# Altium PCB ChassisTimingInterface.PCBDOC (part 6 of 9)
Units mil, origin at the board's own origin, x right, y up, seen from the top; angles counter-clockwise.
Board outline 7007.87 x 4368.85 mil, 10 copper layers (Top Layer, Int1 (GND), Int2 (Sign), Int3 (Sign), Int4 (PWR), Int5 (GND), Int6 (Sign), Int7 (Sign), Int8 (GND), Bottom Layer), stack 54.89 mil thick; 537 components, 525 nets, 2288 pads, 1306 vias.
Unrouted connection lines stored in the file: 373.
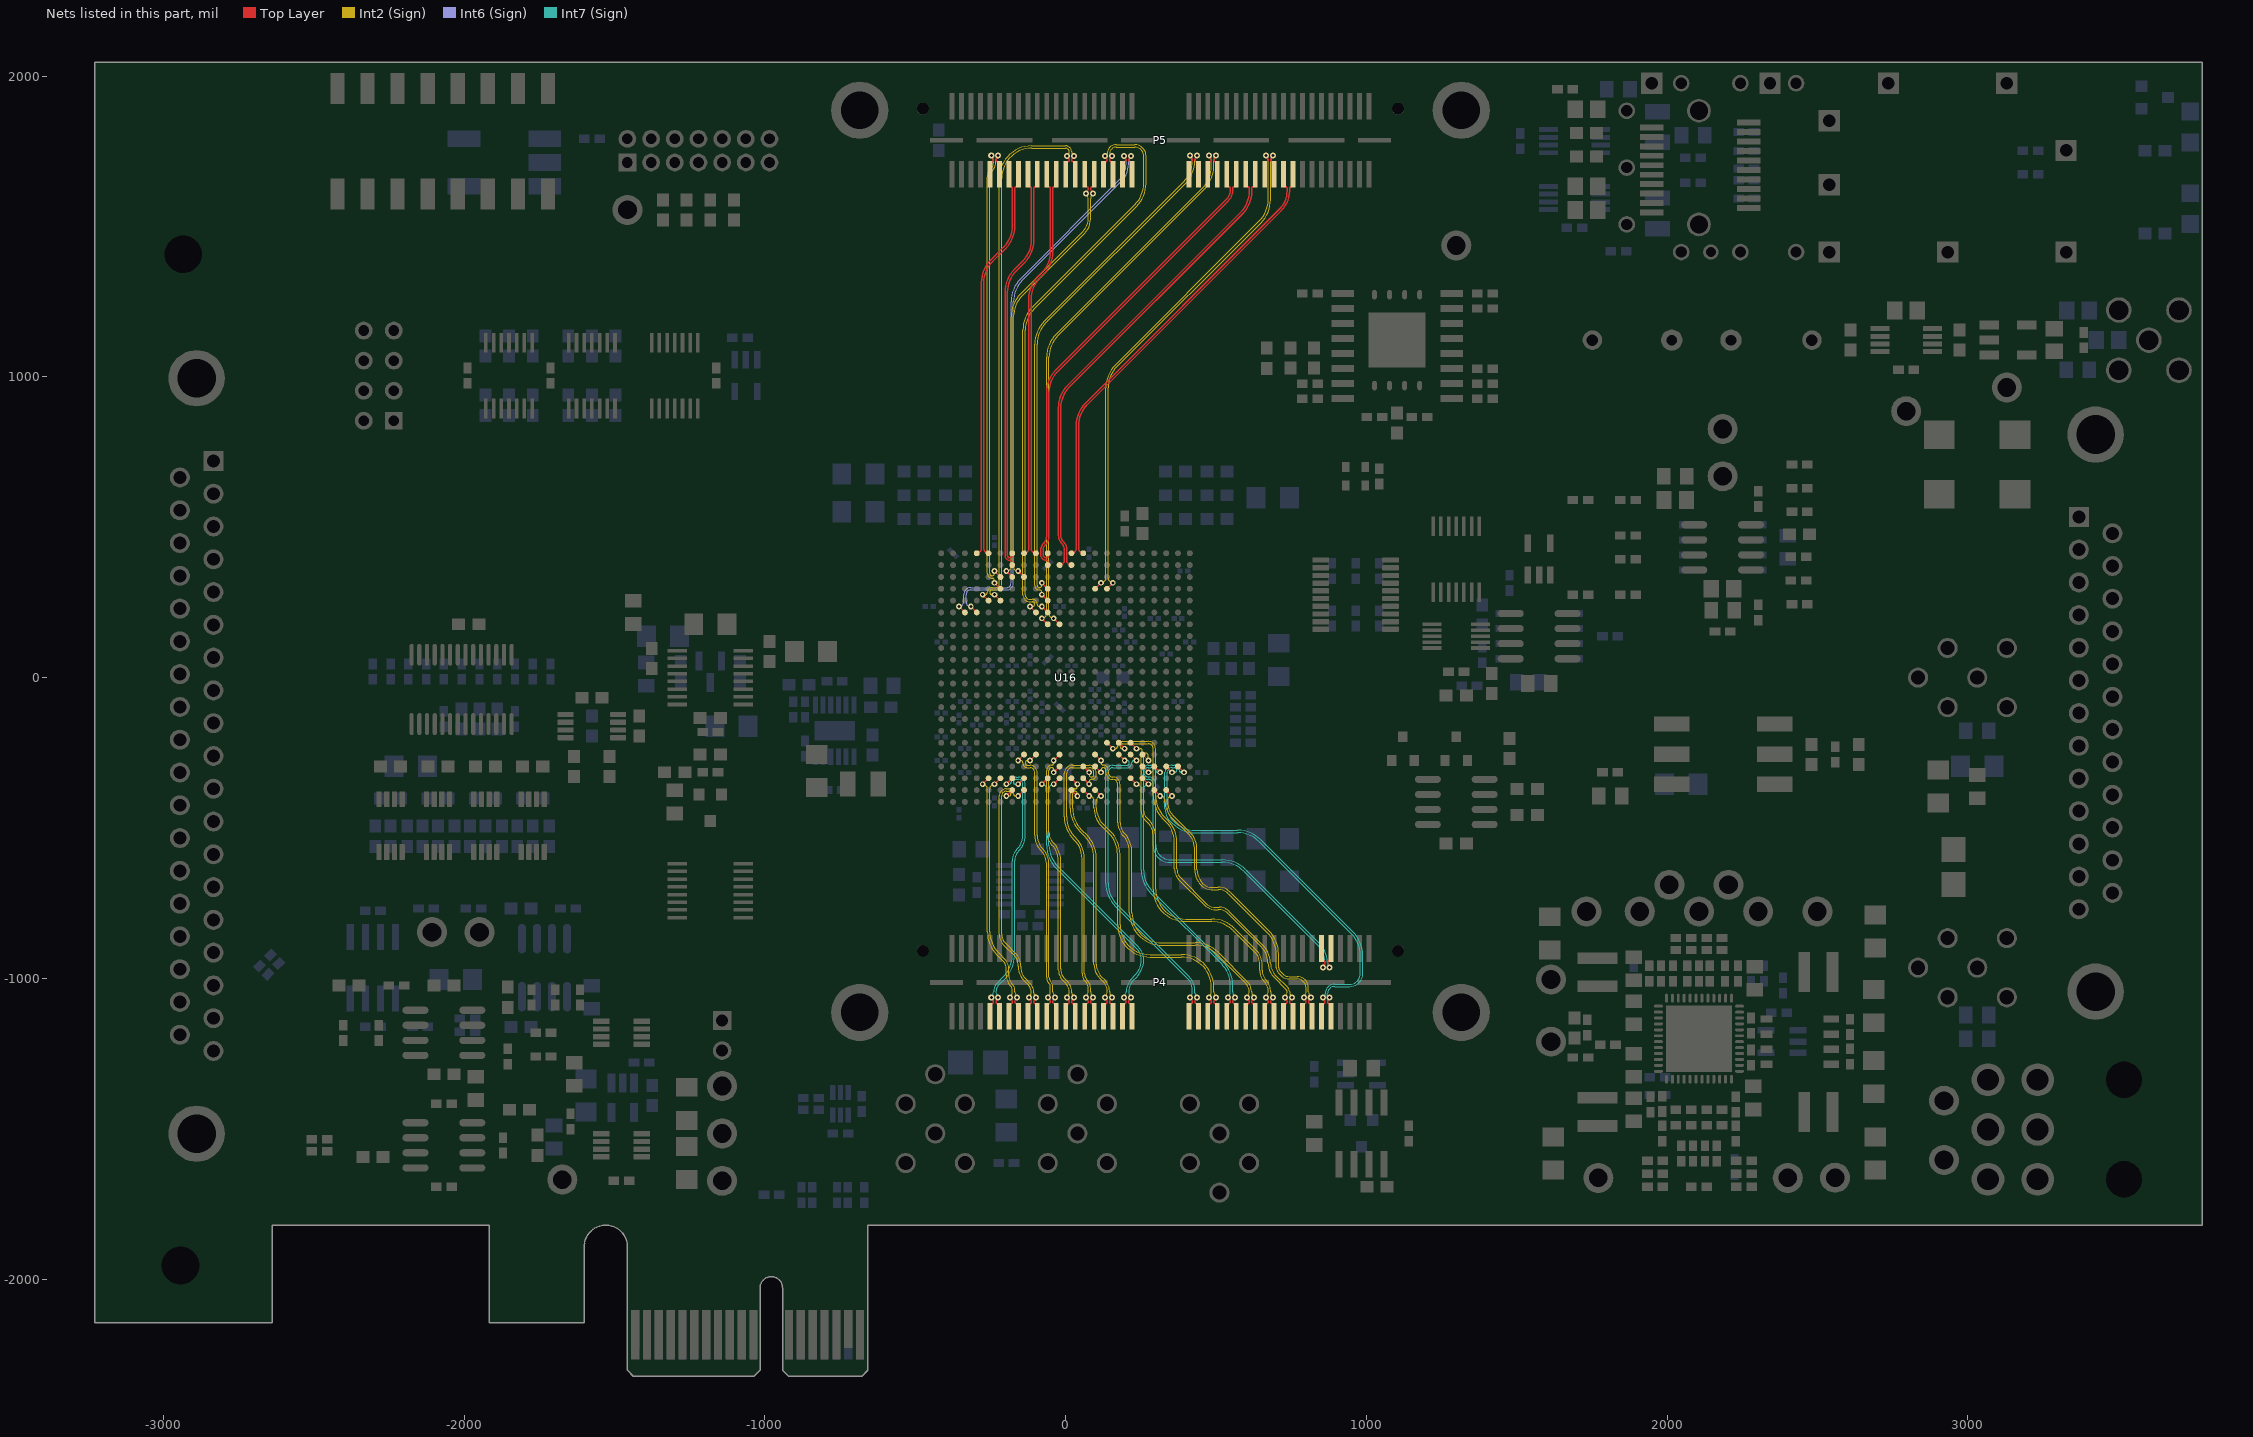
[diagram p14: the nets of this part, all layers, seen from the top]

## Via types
v1: diameter 19, hole 10, Top Layer to Bottom Layer, tented both sides, 667 vias
v2: diameter 20, hole 10, Top Layer to Bottom Layer, tented both sides, 248 vias
v3: diameter 16, hole 10, Top Layer to Bottom Layer, tented both sides, 191 vias
v4: diameter 12, hole 6, Top Layer to Bottom Layer, tented both sides, 85 vias
v5: diameter 19.68, hole 10, Top Layer to Bottom Layer, tented both sides, 50 vias
v6: diameter 17.72, hole 10, Top Layer to Bottom Layer, tented both sides, 19 vias
v7: diameter 19, hole 10, Top Layer to Bottom Layer, 15 vias
v8: diameter 23.62, hole 10, Top Layer to Bottom Layer, tented both sides, 14 vias
v9: diameter 20, hole 10, Top Layer to Bottom Layer, 11 vias
v10: diameter 16, hole 10, Top Layer to Bottom Layer, 3 vias
v11: diameter 22, hole 12, Top Layer to Bottom Layer, tented both sides, 2 vias
v12: diameter 19.02, hole 10, Top Layer to Bottom Layer, tented both sides, 1 vias

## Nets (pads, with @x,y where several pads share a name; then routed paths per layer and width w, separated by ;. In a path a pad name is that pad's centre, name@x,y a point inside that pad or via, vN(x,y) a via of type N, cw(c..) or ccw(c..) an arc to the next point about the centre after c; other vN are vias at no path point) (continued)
S1_16.S16_N: P4.70 U16.W4 | length 1228.2
  Top Layer w5: U16.W4@295.28,-295.28 v1(314.96,-314.96) ; P4.70@851.16,-900.6 851.16,-933.39 ccw(c860.13,-933.39) 853.78,-939.72 855.36,-941.3 ccw(c857.9,-938.76) 857.9,-942.35 cw(c857.9,-945.95) 860.45,-943.41 cw(c855.21,-948.64) 862.61,-948.64 862.61,-949 cw(c850.32,-949) 859.01,-957.69 857.73,-958.98 ccw(c863.31,-964.57) v2(855.41,-964.57)
  Int7 (Sign) w3: v1(314.96,-314.96) 307.15,-314.96 cw(c307.15,-307.09) 299.28,-307.09 ccw(c283.4,-307.09) 283.4,-291.21 275.59,-291.21 ccw(c275.59,-314.96) 251.84,-314.96 ccw(c275.46,-314.96) 275.46,-338.58 275.59,-338.58 cw(c275.59,-354.33) 291.34,-354.33 291.34,-558.43 ccw(c347.21,-558.43) 347.21,-614.3 521.7,-614.3 cw(c521.7,-714.3) 592.41,-643.59 840.03,-891.21 cw(c784.78,-946.46) 862.91,-946.46 cw(c843.97,-946.46) 857.36,-959.86 ccw(c862.07,-964.57) v2(855.41,-964.57)
S1_16.S16_P: P4.72 U16.V4 | length 1201.6
  Top Layer w5: U16.V4@255.91,-295.28 v1(275.59,-314.96) ; v2(878.41,-964.57) ccw(c870.52,-964.57) 876.11,-958.99 874.81,-957.69 cw(c883.51,-949) 871.21,-949 871.21,-948.64 cw(c878.62,-948.64) 873.38,-943.41 cw(c875.93,-945.95) 875.93,-942.35 ccw(c875.93,-938.76) 878.46,-941.31 880.04,-939.73 ccw(c873.7,-933.39) 882.66,-933.39 P4.72@882.66,-900.6
  Int7 (Sign) w3: v1(275.59,-314.96) 283.4,-314.96 ccw(c283.4,-307.09) 291.28,-307.09 ccw(c283.4,-307.09) 283.4,-299.21 275.59,-299.21 ccw(c275.59,-314.96) 259.84,-314.96 ccw(c275.46,-314.96) 275.46,-330.58 275.59,-330.58 cw(c275.59,-354.33) 299.34,-354.33 299.34,-555.12 ccw(c350.52,-555.12) 350.52,-606.3 521.73,-606.3 cw(c521.73,-714.21) 598.04,-637.91 845.7,-885.57 cw(c784.84,-946.44) 870.91,-946.44 ccw(c889.86,-946.46) 876.47,-959.86 cw(c871.76,-964.57) v2(878.41,-964.57)
S17_32.S17_N: P4.11 U16.G3 | length 928.7
  Top Layer w5: v2(-223.92,-1062.99) cw(c-231.82,-1062.99) -226.23,-1068.58 -227.82,-1070.16 ccw(c-219.85,-1078.13) -231.12,-1078.13 ccw(c-223.71,-1078.13) -228.95,-1083.37 ccw(c-226.41,-1080.82) -226.41,-1084.42 cw(c-226.41,-1088.01) -223.87,-1085.47 -222.29,-1087.05 cw(c-228.63,-1093.38) -219.67,-1093.38 P4.11@-219.67,-1126.17 ; v1(-196.85,-354.33) U16.G3@-177.17,-334.65
  Int7 (Sign) w3: v2(-223.92,-1062.99) ccw(c-230.58,-1062.99) -225.87,-1058.28 cw(c-212.47,-1044.89) -231.42,-1044.89 cw(c-198.2,-1044.89) -221.69,-1021.4 -200.89,-1000.6 ccw(c-277.19,-924.31) -169.29,-924.31 -169.29,-609.19 cw(c-123.09,-609.19) -155.76,-576.52 -155.67,-576.44 ccw(c-208.49,-523.62) -133.8,-523.62 -133.8,-354.27 ccw(c-157.48,-354.27) -157.48,-330.58 -163.44,-330.58 ccw(c-163.44,-348.31) -181.17,-348.31 cw(c-187.19,-348.31) -187.19,-354.33 v1(-196.85,-354.33)
S17_32.S17_P: P4.9 U16.H3 | length 903.6
  Top Layer w5: P4.9@-251.17,-1126.17 -251.17,-1093.38 cw(c-242.21,-1093.38) -248.54,-1087.04 -246.97,-1085.47 cw(c-244.43,-1088.01) -244.43,-1084.42 ccw(c-244.43,-1080.82) -241.89,-1083.37 ccw(c-247.12,-1078.13) -239.72,-1078.13 ccw(c-250.98,-1078.13) -243.02,-1070.16 -244.61,-1068.57 cw(c-239.02,-1062.99) v2(-246.92,-1062.99) ; v1(-157.48,-354.33) U16.H3@-137.8,-334.65
  Int7 (Sign) w3: v2(-246.92,-1062.99) cw(c-240.26,-1062.99) -244.97,-1058.28 ccw(c-258.37,-1044.89) -239.42,-1044.89 -239.42,-1044.76 cw(c-198.5,-1044.76) -227.43,-1015.83 -206.58,-994.97 ccw(c-277.29,-924.26) -177.29,-924.26 -177.29,-609.08 cw(c-123.36,-609.08) -161.49,-570.94 -161.42,-570.87 ccw(c-208.79,-523.5) -141.8,-523.5 -141.8,-354.27 ccw(c-157.48,-354.27) -157.48,-338.58 -163.44,-338.58 ccw(c-163.44,-348.31) -173.17,-348.31 ccw(c-167.15,-348.31) -167.15,-354.33 v1(-157.48,-354.33)
S17_32.S18_N: P4.13 U16.E3 | length 843.6
  Top Layer w5: v1(-275.59,-354.33) U16.E3@-255.91,-334.65 ; P4.13@-188.19,-1126.17 -188.19,-1093.38 cw(c-179.22,-1093.38) -185.56,-1087.04 -183.98,-1085.47 cw(c-181.45,-1088.01) -181.45,-1084.42 ccw(c-181.45,-1080.82) -178.9,-1083.37 ccw(c-184.14,-1078.13) -176.74,-1078.13 ccw(c-188,-1078.13) -180.03,-1070.16 -181.63,-1068.57 cw(c-176.04,-1062.99) v2(-183.94,-1062.99)
  Int2 (Sign) w3: v1(-275.59,-354.33) cw(c-275.59,-370.02) -259.91,-370.02 -259.91,-845.03 ccw(c-151.96,-845.03) -228.29,-921.36 -208.17,-941.48 cw(c-235.19,-968.5) -196.98,-968.5 -196.98,-989.31 ccw(c-142.96,-989.31) -181.16,-1027.51 -181.1,-1027.56 cw(c-192.37,-1038.83) -176.44,-1038.83 -176.44,-1044.89 cw(c-195.38,-1044.89) -181.99,-1058.28 ccw(c-177.28,-1062.99) v2(-183.94,-1062.99)
S17_32.S18_P: P4.15 U16.F3 | length 843.6
  Top Layer w5: v1(-236.22,-354.33) U16.F3@-216.54,-334.65 ; v2(-160.94,-1062.99) cw(c-168.83,-1062.99) -163.25,-1068.58 -164.84,-1070.16 ccw(c-156.87,-1078.13) -168.14,-1078.13 ccw(c-160.73,-1078.13) -165.97,-1083.37 ccw(c-163.42,-1080.82) -163.42,-1084.42 cw(c-163.42,-1088.01) -160.89,-1085.47 -159.3,-1087.05 cw(c-165.65,-1093.38) -156.69,-1093.38 P4.15@-156.69,-1126.17
  Int2 (Sign) w3: v1(-236.22,-354.33) ccw(c-236.22,-370.02) -251.91,-370.02 -251.91,-845.01 ccw(c-151.91,-845.01) -222.62,-915.72 -202.45,-935.89 cw(c-234.97,-968.42) -188.98,-968.42 -188.98,-989.24 ccw(c-142.78,-989.24) -175.45,-1021.9 ; -175.42,-1021.92 cw(c-192.29,-1038.79) -168.44,-1038.79 -168.44,-1044.89 ccw(c-149.49,-1044.89) -162.88,-1058.28 cw(c-167.59,-1062.99) v2(-160.94,-1062.99)
S17_32.S19_N: P4.19 U16.G2 | length 871.5
  Top Layer w5: v1(-196.85,-393.7) U16.G2@-177.17,-374.02 ; v2(-97.94,-1062.99) cw(c-105.83,-1062.99) -100.25,-1068.58 -101.84,-1070.16 ccw(c-93.87,-1078.13) -105.14,-1078.13 ccw(c-97.73,-1078.13) -102.97,-1083.37 ccw(c-100.42,-1080.82) -100.42,-1084.42 cw(c-100.42,-1088.01) -97.89,-1085.47 -96.3,-1087.05 cw(c-102.65,-1093.38) -93.69,-1093.38 P4.19@-93.69,-1126.17
  Int2 (Sign) w3: v1(-196.85,-393.7) -189.04,-393.7 ccw(c-189.04,-385.83) -181.17,-385.83 ccw(c-189.04,-385.83) -189.04,-377.95 -196.85,-377.95 ccw(c-196.85,-393.7) -212.6,-393.7 -212.6,-853.38 ccw(c-172.27,-853.38) -200.79,-881.89 -163.5,-919.17 cw(c-197.05,-952.72) -149.61,-952.72 -149.61,-960.05 ccw(c-89.97,-960.05) -132.14,-1002.22 -118.34,-1016.02 cw(c-149.49,-1047.17) -105.44,-1047.17 -105.44,-1047.24 ccw(c-92.18,-1047.24) -101.56,-1056.61 -99.88,-1058.29 cw(c-104.59,-1062.99) v2(-97.94,-1062.99)
S17_32.S19_P: P4.17 U16.H2 | length 896.6
  Top Layer w5: v1(-157.48,-393.7) U16.H2@-137.8,-374.02 ; P4.17@-125.19,-1126.17 -125.19,-1093.38 cw(c-116.22,-1093.38) -122.56,-1087.04 -120.98,-1085.47 cw(c-118.45,-1088.01) -118.45,-1084.42 ccw(c-118.45,-1080.82) -115.9,-1083.37 ccw(c-121.14,-1078.13) -113.74,-1078.13 ccw(c-125,-1078.13) -117.03,-1070.16 -118.63,-1068.57 cw(c-113.04,-1062.99) v2(-120.94,-1062.99)
  Int2 (Sign) w3: v1(-157.48,-393.7) -165.29,-393.7 cw(c-165.29,-385.83) -173.17,-385.83 ccw(c-189.04,-385.83) -189.04,-369.95 -196.85,-369.95 ccw(c-196.85,-393.7) -220.6,-393.7 -220.6,-853.41 ccw(c-172.35,-853.41) -206.47,-887.52 -169.18,-924.81 cw(c-197.13,-952.76) -157.61,-952.76 -157.61,-960.1 ccw(c-90.11,-960.1) -137.84,-1007.83 -124.05,-1021.62 cw(c-149.67,-1047.24) -113.44,-1047.24 cw(c-126.69,-1047.24) -117.31,-1056.61 -118.99,-1058.28 ccw(c-114.28,-1062.99) v2(-120.94,-1062.99)
S17_32.S20_N: P4.21 U16.H5 | length 940.2
  Top Layer w5: v1(-157.48,-275.59) U16.H5@-137.8,-255.91 ; P4.21@-62.2,-1126.17 -62.2,-1093.38 cw(c-53.24,-1093.38) -59.58,-1087.04 -58,-1085.47 cw(c-55.46,-1088.01) -55.46,-1084.42 ccw(c-55.46,-1080.82) -52.92,-1083.37 ccw(c-58.16,-1078.13) -50.75,-1078.13 ccw(c-62.02,-1078.13) -54.05,-1070.16 -55.65,-1068.57 cw(c-50.05,-1062.99) v2(-57.95,-1062.99)
  Int2 (Sign) w3: v1(-157.48,-275.59) -149.67,-275.59 cw(c-149.67,-283.46) -141.8,-283.46 ccw(c-125.92,-283.46) -125.92,-299.34 -117.98,-299.34 cw(c-117.98,-314.96) -102.36,-314.96 -102.36,-523.7 ccw(c-27.72,-523.7) -80.5,-576.48 -80.46,-576.52 cw(c-122.63,-618.69) -62.99,-618.69 -62.99,-996.77 ccw(c-36.19,-996.77) -55.17,-1015.7 -55.12,-1015.75 cw(c-66.38,-1027.01) -50.45,-1027.01 -50.45,-1044.89 cw(c-69.4,-1044.89) -56,-1058.28 ccw(c-51.29,-1062.99) v2(-57.95,-1062.99)
S17_32.S20_P: P4.23 U16.J5 | length 940.2
  Top Layer w5: v1(-118.11,-275.59) U16.J5@-98.43,-255.91 ; v2(-34.95,-1062.99) cw(c-42.85,-1062.99) -37.27,-1068.58 -38.85,-1070.16 ccw(c-30.89,-1078.13) -42.15,-1078.13 ccw(c-34.75,-1078.13) -39.98,-1083.37 ccw(c-37.44,-1080.82) -37.44,-1084.42 cw(c-37.44,-1088.01) -34.91,-1085.47 -33.32,-1087.05 cw(c-39.66,-1093.38) -30.7,-1093.38 P4.23@-30.7,-1126.17
  Int2 (Sign) w3: v1(-118.11,-275.59) -125.92,-275.59 ccw(c-125.92,-283.46) -133.8,-283.46 ccw(c-125.92,-283.46) -125.92,-291.34 -117.98,-291.34 cw(c-117.98,-314.96) -94.36,-314.96 -94.36,-523.65 ccw(c-27.58,-523.65) -74.8,-570.87 -74.76,-570.91 cw(c-122.5,-618.64) -54.99,-618.64 -54.99,-996.74 ccw(c-36.11,-996.74) -49.46,-1010.09 ; -49.43,-1010.12 cw(c-66.28,-1026.97) -42.45,-1026.97 -42.45,-1044.89 ccw(c-23.5,-1044.89) -36.9,-1058.28 cw(c-41.61,-1062.99) v2(-34.95,-1062.99)
S17_32.S21_N: P4.27 U16.L4 | length 910.6
  Top Layer w5: v1(-39.37,-314.96) U16.L4@-19.69,-295.28 ; v2(28.05,-1062.99) cw(c20.15,-1062.99) 25.73,-1068.58 24.15,-1070.16 ccw(c32.11,-1078.13) 20.85,-1078.13 ccw(c28.25,-1078.13) 23.02,-1083.37 ccw(c25.56,-1080.82) 25.56,-1084.42 cw(c25.56,-1088.01) 28.09,-1085.47 29.68,-1087.05 cw(c23.34,-1093.38) 32.3,-1093.38 P4.27@32.3,-1126.17
  Int2 (Sign) w3: v1(-39.37,-314.96) -39.37,-304.98 ccw(c-45.07,-304.98) -45.07,-299.28 ccw(c-45.07,-309.32) -55.12,-309.32 -55.12,-513.16 ccw(c-1.35,-513.16) -39.37,-551.18 cw(c-96.63,-608.48) -15.62,-608.48 -15.62,-968.5 ccw(c33.41,-968.5) -1.26,-1003.17 5.74,-1010.18 cw(c-30,-1045.92) 20.55,-1045.92 20.55,-1047.24 ccw(c33.8,-1047.24) 24.42,-1056.61 26.11,-1058.29 cw(c21.39,-1062.99) v2(28.05,-1062.99)
S17_32.S21_P: P4.25 U16.L5 | length 923.5
  Top Layer w5: v1(-39.37,-275.59) U16.L5@-19.69,-255.91 ; P4.25@0.8,-1126.17 0.8,-1093.38 cw(c9.76,-1093.38) 3.42,-1087.04 5,-1085.47 cw(c7.54,-1088.01) 7.54,-1084.42 ccw(c7.54,-1080.82) 10.08,-1083.37 ccw(c4.84,-1078.13) 12.25,-1078.13 ccw(c0.98,-1078.13) 8.95,-1070.16 7.35,-1068.57 cw(c12.95,-1062.99) v2(5.05,-1062.99)
  Int2 (Sign) w3: v1(-39.37,-275.59) -39.37,-285.57 cw(c-45.07,-285.57) -45.07,-291.28 ccw(c-45.07,-309.32) -63.12,-309.32 -63.12,-513.24 ccw(c-1.53,-513.24) -45.08,-556.79 -45.03,-556.84 cw(c-96.7,-608.51) -23.62,-608.51 -23.62,-971.82 ccw(c25.41,-971.82) -9.26,-1006.49 0,-1015.75 cw(c-30.29,-1046.04) 12.55,-1046.04 12.55,-1047.24 cw(c-0.71,-1047.24) 8.67,-1056.61 7,-1058.28 ccw(c11.71,-1062.99) v2(5.05,-1062.99)
S17_32.S22_N: P4.29 U16.N3 | length 1055.2
  Top Layer w5: U16.N3@59.06,-334.65 v1(78.74,-354.33) ; P4.29@63.78,-1126.17 63.78,-1093.38 cw(c72.74,-1093.38) 66.41,-1087.04 67.98,-1085.47 cw(c70.52,-1088.01) 70.52,-1084.42 ccw(c70.52,-1080.82) 73.06,-1083.37 ccw(c67.83,-1078.13) 75.23,-1078.13 ccw(c63.97,-1078.13) 71.93,-1070.16 70.34,-1068.57 cw(c75.93,-1062.99) v2(68.03,-1062.99)
  Int2 (Sign) w3: v2(68.03,-1062.99) cw(c74.69,-1062.99) 69.98,-1058.28 ccw(c56.58,-1044.89) 75.53,-1044.89 75.53,-1032.58 ccw(c46.16,-1032.58) 66.93,-1011.81 66.88,-1011.76 cw(c95.26,-983.37) 55.12,-983.37 55.12,-602.27 ccw(c-31.4,-602.27) 29.78,-541.09 27.55,-538.87 cw(c103.88,-462.54) -4.06,-462.54 -4.06,-318.9 cw(c23.62,-318.9) 23.62,-291.21 78.74,-291.21 cw(c78.74,-314.96) 102.49,-314.96 102.49,-322.77 cw(c86.61,-322.77) 86.61,-338.65 ccw(c86.61,-346.52) 78.74,-346.52 v1(78.74,-354.33)
S17_32.S22_P: P4.31 U16.N4 | length 1017.5
  Top Layer w5: U16.N4@59.06,-295.28 v1(78.74,-314.96) ; v2(91.03,-1062.99) cw(c83.13,-1062.99) 88.72,-1068.58 87.13,-1070.16 ccw(c95.1,-1078.13) 83.83,-1078.13 ccw(c91.24,-1078.13) 86,-1083.37 ccw(c88.54,-1080.82) 88.54,-1084.42 cw(c88.54,-1088.01) 91.08,-1085.47 92.66,-1087.05 cw(c86.32,-1093.38) 95.28,-1093.38 P4.31@95.28,-1126.17
  Int2 (Sign) w3: 72.62,-1006.19 cw(c46.27,-1032.53) 83.53,-1032.53 83.53,-1044.89 ccw(c102.48,-1044.89) 89.08,-1058.28 cw(c84.37,-1062.99) v2(91.03,-1062.99) ; 72.59,-1006.15 cw(c95.44,-983.3) 63.12,-983.3 63.12,-602.24 ccw(c-31.33,-602.24) 35.46,-535.46 33.23,-533.23 cw(c103.94,-462.52) 3.94,-462.52 3.94,-318.9 cw(c23.62,-318.9) 23.62,-299.21 78.74,-299.21 cw(c78.74,-314.96) 94.49,-314.96 94.49,-322.77 cw(c86.61,-322.77) 86.61,-330.65 cw(c86.61,-322.77) 78.74,-322.77 v1(78.74,-314.96)
S17_32.S23_N: P4.35 U16.M2 | length 847.6
  Top Layer w5: U16.M2@19.69,-374.02 v1(39.37,-393.7) ; v2(154.03,-1062.99) cw(c146.13,-1062.99) 151.72,-1068.58 150.13,-1070.16 ccw(c158.1,-1078.13) 146.83,-1078.13 ccw(c154.24,-1078.13) 149,-1083.37 ccw(c151.54,-1080.82) 151.54,-1084.42 cw(c151.54,-1088.01) 154.08,-1085.47 155.66,-1087.05 cw(c149.32,-1093.38) 158.28,-1093.38 P4.35@158.28,-1126.17
  Int2 (Sign) w3: v1(39.37,-393.7) 39.37,-385.89 ccw(c31.5,-385.89) 31.5,-378.02 ccw(c31.5,-385.89) 23.62,-385.89 23.62,-434.96 ccw(c123.62,-434.96) 52.91,-505.67 71.52,-524.28 cw(c-2.93,-598.73) 102.36,-598.73 102.36,-952.76 ccw(c160.59,-952.76) 119.42,-993.93 130.88,-1005.39 cw(c93.08,-1043.19) 146.53,-1043.19 146.53,-1044.89 ccw(c165.48,-1044.89) 152.08,-1058.28 cw(c147.37,-1062.99) v2(154.03,-1062.99)
S17_32.S23_P: P4.33 U16.M3 | length 860.1
  Top Layer w5: U16.M3@19.69,-334.65 v1(39.37,-354.33) ; P4.33@126.78,-1126.17 126.78,-1093.38 cw(c135.74,-1093.38) 129.41,-1087.04 130.98,-1085.47 cw(c133.52,-1088.01) 133.52,-1084.42 ccw(c133.52,-1080.82) 136.06,-1083.37 ccw(c130.83,-1078.13) 138.23,-1078.13 ccw(c126.97,-1078.13) 134.93,-1070.16 133.34,-1068.57 cw(c138.93,-1062.99) v2(131.03,-1062.99)
  Int2 (Sign) w3: v1(39.37,-354.33) 39.37,-362.14 cw(c31.5,-362.14) 31.5,-370.02 ccw(c31.5,-385.89) 15.62,-385.89 15.62,-434.98 ccw(c123.56,-434.98) 47.24,-511.31 65.8,-529.87 cw(c-3.17,-598.83) 94.36,-598.83 94.36,-952.78 ccw(c160.53,-952.78) 113.74,-999.57 125.13,-1010.96 cw(c92.78,-1043.31) 138.53,-1043.31 138.53,-1044.89 cw(c119.58,-1044.89) 132.98,-1058.28 ccw(c137.69,-1062.99) v2(131.03,-1062.99)
S17_32.S24_N: P4.37 U16.K3 | length 957
  Top Layer w5: v1(-78.74,-354.33) U16.K3@-59.06,-334.65 ; P4.37@189.76,-1126.17 189.76,-1093.38 cw(c198.73,-1093.38) 192.39,-1087.04 193.97,-1085.47 cw(c196.5,-1088.01) 196.5,-1084.42 ccw(c196.5,-1080.82) 199.05,-1083.37 ccw(c193.81,-1078.13) 201.21,-1078.13 ccw(c189.95,-1078.13) 197.92,-1070.16 196.32,-1068.57 cw(c201.91,-1062.99) v2(194.01,-1062.99)
  Int7 (Sign) w3: v1(-78.74,-354.33) cw(c-78.74,-370.02) -63.06,-370.02 -63.06,-557.09 ccw(c44.89,-557.09) -31.46,-633.4 236.48,-901.34 cw(c199.09,-938.73) 251.97,-938.73 cw(c178.89,-938.73) 230.56,-990.41 219.48,-1001.49 ccw(c262.85,-1044.86) 201.51,-1044.86 ; v2(194.01,-1062.99) cw(c200.67,-1062.99) 195.96,-1058.28 ccw(c182.57,-1044.89) 201.51,-1044.89
S17_32.S24_P: P4.39 U16.L3 | length 957
  Top Layer w5: v1(-39.37,-354.33) U16.L3@-19.69,-334.65 ; v2(217.01,-1062.99) cw(c209.12,-1062.99) 214.7,-1068.58 213.11,-1070.16 ccw(c221.08,-1078.13) 209.81,-1078.13 ccw(c217.22,-1078.13) 211.98,-1083.37 ccw(c214.53,-1080.82) 214.53,-1084.42 cw(c214.53,-1088.01) 217.06,-1085.47 218.65,-1087.05 cw(c212.3,-1093.38) 221.26,-1093.38 P4.39@221.26,-1126.17
  Int7 (Sign) w3: v1(-39.37,-354.33) ccw(c-39.37,-370.02) -55.06,-370.02 -55.06,-557.07 ccw(c44.94,-557.07) -25.77,-627.78 242.21,-895.75 cw(c199.33,-938.63) 259.97,-938.63 259.97,-938.74 cw(c178.91,-938.74) 236.23,-996.06 225.15,-1007.13 ccw(c262.91,-1044.89) 209.51,-1044.89 ccw(c228.46,-1044.89) 215.07,-1058.28 cw(c210.36,-1062.99) v2(217.01,-1062.99)
S17_32.S25_N: P4.43 U16.U5 | length 1078.2
  Top Layer w5: U16.U5@216.54,-255.91 v1(236.22,-275.59) ; v2(437.48,-1062.99) cw(c429.58,-1062.99) 435.17,-1068.58 433.58,-1070.16 ccw(c441.55,-1078.13) 430.28,-1078.13 ccw(c437.69,-1078.13) 432.45,-1083.37 ccw(c434.99,-1080.82) 434.99,-1084.42 cw(c434.99,-1088.01) 437.53,-1085.47 439.11,-1087.05 cw(c432.77,-1093.38) 441.73,-1093.38 P4.43@441.73,-1126.17
  Int7 (Sign) w3: v1(236.22,-275.59) 228.41,-275.59 ccw(c228.41,-283.46) 220.54,-283.46 cw(c204.66,-283.46) 204.66,-299.34 157.48,-299.34 ccw(c157.48,-315.09) 141.73,-315.09 141.73,-683.49 ccw(c241.73,-683.49) 171.02,-754.2 411.2,-994.38 cw(c365.87,-1039.71) 429.98,-1039.71 429.98,-1047.24 ccw(c443.24,-1047.24) 433.86,-1056.61 435.54,-1058.29 cw(c430.82,-1062.99) v2(437.48,-1062.99)
S17_32.S25_P: P4.41 U16.T5 | length 1078.2
  Top Layer w5: U16.T5@177.17,-255.91 v1(196.85,-275.59) ; P4.41@410.23,-1126.17 410.23,-1093.38 cw(c419.19,-1093.38) 412.86,-1087.04 414.43,-1085.47 cw(c416.97,-1088.01) 416.97,-1084.42 ccw(c416.97,-1080.82) 419.51,-1083.37 ccw(c414.28,-1078.13) 421.68,-1078.13 ccw(c410.42,-1078.13) 418.38,-1070.16 416.79,-1068.57 cw(c422.38,-1062.99) v2(414.48,-1062.99)
  Int7 (Sign) w3: v1(196.85,-275.59) 204.66,-275.59 cw(c204.66,-283.46) 212.54,-283.46 cw(c204.66,-283.46) 204.66,-291.34 157.48,-291.34 ccw(c157.48,-315.09) 133.73,-315.09 133.73,-683.51 ccw(c241.67,-683.51) 165.35,-759.84 405.51,-1000 cw(c365.75,-1039.76) 421.98,-1039.76 421.98,-1047.24 cw(c408.73,-1047.24) 418.11,-1056.61 416.43,-1058.28 ccw(c421.14,-1062.99) v2(414.48,-1062.99)
S17_32.S26_N: P4.45 U16.N2 | length 1026.1
  Top Layer w5: U16.N2@59.06,-374.02 v1(78.74,-393.7) ; P4.45@473.21,-1126.17 473.21,-1093.38 cw(c482.18,-1093.38) 475.84,-1087.04 477.42,-1085.47 cw(c479.95,-1088.01) 479.95,-1084.42 ccw(c479.95,-1080.82) 482.5,-1083.37 ccw(c477.26,-1078.13) 484.66,-1078.13 ccw(c473.4,-1078.13) 481.37,-1070.16 479.77,-1068.57 cw(c485.36,-1062.99) v2(477.46,-1062.99)
  Int2 (Sign) w3: v1(78.74,-393.7) cw(c78.74,-409.39) 94.43,-409.39 94.43,-433.09 ccw(c178.56,-433.09) 119.07,-492.59 143.94,-517.46 cw(c73.23,-588.17) 173.23,-588.17 173.23,-821.13 ccw(c281.23,-821.13) 281.23,-929.13 384.96,-929.13 cw(c384.96,-1029.13) 484.96,-1029.13 484.96,-1044.89 cw(c466.02,-1044.89) 479.41,-1058.28 ccw(c484.12,-1062.99) v2(477.46,-1062.99)
S17_32.S26_P: P4.47 U16.P2 | length 1026.1
  Top Layer w5: U16.P2@98.43,-374.02 v1(118.11,-393.7) ; v2(500.46,-1062.99) cw(c492.57,-1062.99) 498.15,-1068.58 496.56,-1070.16 ccw(c504.53,-1078.13) 493.26,-1078.13 ccw(c500.67,-1078.13) 495.43,-1083.37 ccw(c497.98,-1080.82) 497.98,-1084.42 cw(c497.98,-1088.01) 500.51,-1085.47 502.1,-1087.05 cw(c495.75,-1093.38) 504.71,-1093.38 P4.47@504.71,-1126.17
  Int2 (Sign) w3: v1(118.11,-393.7) ccw(c118.11,-409.39) 102.43,-409.39 102.43,-433.07 ccw(c178.62,-433.07) 124.74,-486.95 149.67,-511.87 cw(c73.47,-588.07) 181.23,-588.07 181.23,-821.13 ccw(c281.23,-821.13) 281.23,-921.13 384.96,-921.13 cw(c384.96,-1029.13) 492.96,-1029.13 492.96,-1044.89 ccw(c511.91,-1044.89) 498.52,-1058.28 cw(c493.81,-1062.99) v2(500.46,-1062.99)
S17_32.S27_N: P4.51 U16.V3 | length 932
  Top Layer w5: U16.V3@255.91,-334.65 v1(275.59,-354.33) ; v2(563.46,-1062.99) cw(c555.57,-1062.99) 561.15,-1068.58 559.56,-1070.16 ccw(c567.53,-1078.13) 556.26,-1078.13 ccw(c563.67,-1078.13) 558.43,-1083.37 ccw(c560.98,-1080.82) 560.98,-1084.42 cw(c560.98,-1088.01) 563.51,-1085.47 565.1,-1087.05 cw(c558.75,-1093.38) 567.71,-1093.38 P4.51@567.71,-1126.17
  Int7 (Sign) w3: v1(275.59,-354.33) ccw(c275.59,-370.02) 259.91,-370.02 259.91,-640.24 ccw(c359.91,-640.24) 289.2,-710.95 524.36,-946.11 cw(c448.05,-1022.42) 555.96,-1022.42 555.96,-1044.89 ccw(c574.91,-1044.89) 561.52,-1058.28 cw(c556.81,-1062.99) v2(563.46,-1062.99)
S17_32.S27_P: P4.49 U16.U3 | length 932
  Top Layer w5: U16.U3@216.54,-334.65 v1(236.22,-354.33) ; P4.49@536.21,-1126.17 536.21,-1093.38 cw(c545.18,-1093.38) 538.84,-1087.04 540.42,-1085.47 cw(c542.95,-1088.01) 542.95,-1084.42 ccw(c542.95,-1080.82) 545.5,-1083.37 ccw(c540.26,-1078.13) 547.66,-1078.13 ccw(c536.4,-1078.13) 544.37,-1070.16 542.77,-1068.57 cw(c548.36,-1062.99) v2(540.46,-1062.99)
  Int7 (Sign) w3: v1(236.22,-354.33) cw(c236.22,-370.02) 251.91,-370.02 251.91,-640.27 ccw(c359.85,-640.27) 283.52,-716.59 518.68,-951.75 cw(c447.96,-1022.46) 547.96,-1022.46 547.96,-1044.89 cw(c529.02,-1044.89) 542.41,-1058.28 ccw(c547.12,-1062.99) v2(540.46,-1062.99)
S17_32.S28_N: P4.53 U16.P4 | length 1186.9
  Top Layer w5: U16.P4@98.43,-295.28 v1(118.11,-314.96) ; P4.53@599.2,-1126.17 599.2,-1093.38 cw(c608.16,-1093.38) 601.82,-1087.04 603.4,-1085.47 cw(c605.94,-1088.01) 605.94,-1084.42 ccw(c605.94,-1080.82) 608.48,-1083.37 ccw(c603.24,-1078.13) 610.65,-1078.13 ccw(c599.38,-1078.13) 607.35,-1070.16 605.75,-1068.57 cw(c611.35,-1062.99) v2(603.45,-1062.99)
  Int2 (Sign) w3: v1(118.11,-314.96) 118.11,-307.15 cw(c125.98,-307.15) 125.98,-299.28 cw(c125.98,-307.15) 133.86,-307.15 133.86,-315.09 ccw(c157.48,-315.09) 157.48,-338.71 157.61,-338.71 cw(c157.61,-354.33) 173.23,-354.33 173.23,-482.04 ccw(c234.39,-482.04) 191.14,-525.29 cw(c139.34,-577.09) 191.19,-525.34 cw(c139.34,-577.09) 212.6,-577.09 212.6,-781.76 ccw(c320.6,-781.76) 320.6,-889.76 431.02,-889.76 cw(c431.02,-989.76) 501.73,-919.05 599.2,-1016.52 cw(c570.84,-1044.89) 610.95,-1044.89 cw(c592,-1044.89) 605.4,-1058.28 ccw(c610.11,-1062.99) v2(603.45,-1062.99)
S17_32.S28_P: P4.55 U16.P5 | length 1199.5
  Top Layer w5: U16.P5@98.43,-255.91 v1(118.11,-275.59) ; v2(626.45,-1062.99) cw(c618.55,-1062.99) 624.13,-1068.58 622.55,-1070.16 ccw(c630.51,-1078.13) 619.25,-1078.13 ccw(c626.65,-1078.13) 621.42,-1083.37 ccw(c623.96,-1080.82) 623.96,-1084.42 cw(c623.96,-1088.01) 626.49,-1085.47 628.08,-1087.05 cw(c621.74,-1093.38) 630.7,-1093.38 P4.55@630.7,-1126.17
  Int2 (Sign) w3: v1(118.11,-275.59) 118.11,-283.4 ccw(c125.98,-283.4) 125.98,-291.28 cw(c125.98,-307.15) 141.86,-307.15 141.86,-315.09 ccw(c157.48,-315.09) 157.48,-330.71 157.61,-330.71 cw(c157.61,-354.33) 181.23,-354.33 181.23,-481.97 ccw(c234.56,-481.97) 196.85,-519.68 196.91,-519.75 cw(c139.73,-576.93) 196.96,-519.79 cw(c139.73,-576.93) 220.6,-576.93 220.6,-781.76 ccw(c320.6,-781.76) 320.6,-881.76 431.05,-881.76 cw(c431.05,-989.68) 507.36,-913.37 604.91,-1010.92 cw(c571.03,-1044.81) 618.95,-1044.81 618.95,-1044.89 ccw(c637.9,-1044.89) 624.5,-1058.28 cw(c619.79,-1062.99) v2(626.45,-1062.99)
S17_32.S29_N: P4.59 U16.V5 | length 1196.5
  Top Layer w5: U16.V5@255.91,-255.91 v1(275.59,-275.59) ; v2(689.45,-1062.99) cw(c681.55,-1062.99) 687.13,-1068.58 685.55,-1070.16 ccw(c693.51,-1078.13) 682.25,-1078.13 ccw(c689.65,-1078.13) 684.42,-1083.37 ccw(c686.96,-1080.82) 686.96,-1084.42 cw(c686.96,-1088.01) 689.49,-1085.47 691.08,-1087.05 cw(c684.74,-1093.38) 693.7,-1093.38 P4.59@693.7,-1126.17
  Int2 (Sign) w3: v1(275.59,-275.59) 275.59,-259.84 ccw(c267.72,-259.84) 267.72,-251.97 ccw(c267.72,-259.84) 262.1,-254.32 ccw(c267.56,-259.78) 259.84,-259.78 259.84,-444.88 ccw(c288.36,-444.88) 268.19,-465.04 279.62,-476.47 ; 279.62,-476.47 cw(c232.01,-524.08) 299.34,-524.08 299.34,-703.02 ccw(c399.34,-703.02) 399.34,-803.02 486.17,-803.02 cw(c486.17,-910.94) 562.48,-834.63 637.28,-909.43 cw(c598.02,-948.69) 653.54,-948.69 653.54,-973.44 ccw(c699.86,-973.44) 667.11,-1006.19 cw(c631.29,-1042.01) 681.95,-1042.01 681.95,-1044.89 ccw(c700.9,-1044.89) 687.5,-1058.28 cw(c682.79,-1062.99) v2(689.45,-1062.99)
S17_32.S29_P: P4.57 U16.U6 | length 1196.8
  Top Layer w5: U16.U6@216.54,-216.54 v1(236.22,-236.22) ; P4.57@662.2,-1126.17 662.2,-1093.38 cw(c671.16,-1093.38) 664.82,-1087.04 666.4,-1085.47 cw(c668.94,-1088.01) 668.94,-1084.42 ccw(c668.94,-1080.82) 671.48,-1083.37 ccw(c666.24,-1078.13) 673.65,-1078.13 ccw(c662.38,-1078.13) 670.35,-1070.16 668.75,-1068.57 cw(c674.35,-1062.99) v2(666.45,-1062.99)
  Int2 (Sign) w3: v1(236.22,-236.22) 248.03,-236.22 cw(c248.03,-244.09) 255.91,-244.09 255.91,-247.64 cw(c252.91,-247.64) 255.55,-249.05 254.5,-251.02 ccw(c267.56,-259.78) 251.84,-259.78 251.84,-444.91 ccw(c288.3,-444.91) 262.52,-470.68 ; 262.52,-470.68 273.87,-482.03 cw(c231.7,-524.21) 291.34,-524.21 291.34,-703.02 ccw(c399.34,-703.02) 399.34,-811.02 486.14,-811.02 cw(c486.14,-911.02) 556.85,-840.31 631.53,-915 cw(c597.72,-948.82) 645.54,-948.82 645.54,-973.49 ccw(c699.73,-973.49) 661.42,-1011.81 cw(c631.17,-1042.06) 673.95,-1042.06 673.95,-1044.89 cw(c655,-1044.89) 668.4,-1058.28 ccw(c673.11,-1062.99) v2(666.45,-1062.99)
S17_32.S30_N: P4.61 U16.T6 | length 1263.6
  Top Layer w5: U16.T6@177.17,-216.54 v1(196.85,-236.22) ; P4.61@725.18,-1126.17 725.18,-1093.38 cw(c734.14,-1093.38) 727.81,-1087.04 729.38,-1085.47 cw(c731.92,-1088.01) 731.92,-1084.42 ccw(c731.92,-1080.82) 734.46,-1083.37 ccw(c729.23,-1078.13) 736.63,-1078.13 ccw(c725.37,-1078.13) 733.33,-1070.16 731.74,-1068.57 cw(c737.33,-1062.99) v2(729.43,-1062.99)
  Int2 (Sign) w3: v1(196.85,-236.22) 189.04,-236.22 cw(c189.04,-228.35) 181.17,-228.35 cw(c189.04,-228.35) 189.04,-220.47 275.59,-220.47 cw(c275.59,-236.22) 291.34,-236.22 291.34,-392.3 ccw(c399.28,-392.3) 322.95,-468.62 334.65,-480.31 cw(c268.11,-546.85) 362.2,-546.85 362.2,-636.37 ccw(c411.97,-636.37) 376.78,-671.56 ; 376.84,-671.62 460.81,-755.59 ccw(c499.89,-716.51) 499.89,-771.78 507.87,-771.78 cw(c507.87,-819.61) 541.69,-785.79 650.69,-894.78 cw(c596.58,-948.89) 673.1,-948.82 cw(c596.58,-948.89) 673.1,-948.89 ccw(c737.65,-948.89) 692.01,-994.53 733.09,-1035.62 cw(c723.83,-1044.89) 736.93,-1044.89 cw(c717.98,-1044.89) 731.38,-1058.28 ccw(c736.09,-1062.99) v2(729.43,-1062.99)
S17_32.S30_P: P4.63 U16.R6 | length 1289.1
  Top Layer w5: U16.R6@137.8,-216.54 v1(157.48,-236.22) ; v2(752.43,-1062.99) cw(c744.53,-1062.99) 750.12,-1068.58 748.53,-1070.16 ccw(c756.5,-1078.13) 745.23,-1078.13 ccw(c752.64,-1078.13) 747.4,-1083.37 ccw(c749.94,-1080.82) 749.94,-1084.42 cw(c749.94,-1088.01) 752.48,-1085.47 754.06,-1087.05 cw(c747.72,-1093.38) 756.68,-1093.38 P4.63@756.68,-1126.17
  Int2 (Sign) w3: v1(157.48,-236.22) 165.29,-236.22 ccw(c165.29,-228.35) 173.17,-228.35 cw(c189.04,-228.35) 189.04,-212.47 275.59,-212.47 cw(c275.59,-236.22) 299.34,-236.22 299.34,-392.27 ccw(c399.34,-392.27) 328.63,-462.98 340.43,-474.78 cw(c268.54,-546.67) 370.2,-546.67 370.2,-636.28 ccw(c412.18,-636.28) 382.49,-665.96 466.4,-749.86 ccw(c500,-716.26) 500,-763.78 511.19,-763.78 cw(c511.19,-811.61) 544.99,-777.77 656.46,-889.24 cw(c596.96,-948.74) 681.1,-948.74 681.1,-948.82 ccw(c737.83,-948.82) 697.72,-988.93 738.79,-1030 cw(c723.97,-1044.83) 744.93,-1044.83 744.93,-1044.89 ccw(c763.88,-1044.89) 750.48,-1058.28 cw(c745.77,-1062.99) v2(752.43,-1062.99)
S17_32.S31_N: P4.67 U16.Y2 | length 1019.5
  Top Layer w5: U16.Y2@334.65,-374.02 v1(354.33,-393.7) ; v2(815.43,-1062.99) cw(c807.53,-1062.99) 813.12,-1068.58 811.53,-1070.16 ccw(c819.5,-1078.13) 808.23,-1078.13 ccw(c815.64,-1078.13) 810.4,-1083.37 ccw(c812.94,-1080.82) 812.94,-1084.42 cw(c812.94,-1088.01) 815.48,-1085.47 817.06,-1087.05 cw(c810.72,-1093.38) 819.68,-1093.38 P4.67@819.68,-1126.17
  Int2 (Sign) w3: v1(354.33,-393.7) ccw(c354.33,-409.39) 338.65,-409.39 338.65,-413.39 ccw(c401.83,-413.39) 357.15,-458.06 416.78,-517.69 cw(c367.65,-566.82) 437.13,-566.82 437.13,-637.82 ccw(c503.91,-637.82) 456.69,-685.04 ccw(c485.21,-656.52) 485.21,-696.85 507.91,-696.85 cw(c507.91,-752.59) 547.33,-713.18 677.1,-842.95 cw(c600.9,-919.15) 708.66,-919.15 708.66,-964.79 ccw(c724.74,-964.79) 713.37,-976.16 722.25,-985.04 ccw(c743.7,-963.59) 743.7,-993.93 770.15,-993.93 cw(c770.15,-1031.69) 796.86,-1004.99 797.74,-1005.87 cw(c773.14,-1030.47) 807.93,-1030.47 807.93,-1044.89 ccw(c826.88,-1044.89) 813.48,-1058.28 cw(c808.77,-1062.99) v2(815.43,-1062.99)
S17_32.S31_P: P4.65 U16.W2 | length 1019.3
  Top Layer w5: U16.W2@295.28,-374.02 v1(314.96,-393.7) ; P4.65@788.18,-1126.17 788.18,-1093.38 cw(c797.14,-1093.38) 790.81,-1087.04 792.38,-1085.47 cw(c794.92,-1088.01) 794.92,-1084.42 ccw(c794.92,-1080.82) 797.46,-1083.37 ccw(c792.23,-1078.13) 799.63,-1078.13 ccw(c788.37,-1078.13) 796.33,-1070.16 794.74,-1068.57 cw(c800.33,-1062.99) v2(792.43,-1062.99)
  Int2 (Sign) w3: v1(314.96,-393.7) cw(c314.96,-409.39) 330.65,-409.39 330.65,-413.41 ccw(c401.77,-413.41) 351.48,-463.7 411.06,-523.28 cw(c367.4,-566.93) 429.13,-566.93 429.13,-637.88 ccw(c503.77,-637.88) 451,-690.66 451.09,-690.75 ccw(c485.13,-656.7) 485.13,-704.85 507.87,-704.85 cw(c507.87,-752.68) 541.69,-718.86 671.37,-848.54 cw(c600.66,-919.25) 700.66,-919.25 700.66,-964.87 ccw(c724.56,-964.87) 707.65,-981.76 716.6,-990.7 ccw(c743.7,-963.59) 716.66,-990.77 ccw(c743.7,-963.59) 743.62,-1001.93 ccw(c743.7,-963.59) 743.7,-1001.93 770.14,-1001.93 cw(c770.14,-1031.71) 791.21,-1010.65 cw(c770.14,-1031.72) 799.93,-1031.72 799.93,-1044.89 cw(c780.98,-1044.89) 794.38,-1058.28 ccw(c799.09,-1062.99) v2(792.43,-1062.99)
S17_32.S32_N: P4.69 U16.AA4 | length 1416.8
  Top Layer w5: U16.AA4@374.02,-295.28 v1(393.7,-314.96) ; P4.69@851.16,-1126.17 851.16,-1093.38 cw(c860.13,-1093.38) 853.79,-1087.04 855.37,-1085.47 cw(c857.9,-1088.01) 857.9,-1084.42 ccw(c857.9,-1080.82) 860.45,-1083.37 ccw(c855.21,-1078.13) 862.61,-1078.13 ccw(c851.35,-1078.13) 859.32,-1070.16 857.72,-1068.57 cw(c863.31,-1062.99) v2(855.41,-1062.99)
  Int7 (Sign) w3: v1(393.7,-314.96) 385.89,-314.96 cw(c385.89,-307.09) 378.02,-307.09 ccw(c362.14,-307.09) 362.14,-291.21 354.33,-291.21 ccw(c354.33,-314.96) 330.58,-314.96 330.58,-434.46 ccw(c392.25,-434.46) 348.64,-478.07 355.35,-484.77 ccw(c430.43,-409.69) 430.43,-515.87 573.13,-515.87 cw(c573.13,-615.87) 643.84,-545.16 681.1,-582.43 681.1,-582.68 951.03,-852.6 cw(c880.31,-923.31) 980.31,-923.31 980.31,-984.25 cw(c945.01,-984.25) 945.01,-1019.56 894.54,-1019.56 ccw(c894.54,-1051.18) 862.91,-1051.18 862.91,-1055.49 cw(c855.41,-1055.49) v2(855.41,-1062.99)
S17_32.S32_P: P4.71 U16.Y4 | length 1391.8
  Top Layer w5: U16.Y4@334.65,-295.28 v1(354.33,-314.96) ; v2(878.41,-1062.99) cw(c870.52,-1062.99) 876.1,-1068.58 874.51,-1070.16 ccw(c882.48,-1078.13) 871.21,-1078.13 ccw(c878.62,-1078.13) 873.38,-1083.37 ccw(c875.93,-1080.82) 875.93,-1084.42 cw(c875.93,-1088.01) 878.46,-1085.47 880.05,-1087.05 cw(c873.7,-1093.38) 882.66,-1093.38 P4.71@882.66,-1126.17
  Int7 (Sign) w3: v1(354.33,-314.96) 362.14,-314.96 ccw(c362.14,-307.09) 370.02,-307.09 ccw(c362.14,-307.09) 362.14,-299.21 354.33,-299.21 ccw(c354.33,-314.96) 338.58,-314.96 338.58,-434.42 ccw(c392.35,-434.42) 354.33,-472.44 360.99,-479.1 ccw(c430.46,-409.63) 430.46,-507.87 573.16,-507.87 cw(c573.16,-615.79) 649.47,-539.48 686.76,-576.77 687.01,-576.77 956.4,-846.16 cw(c879.35,-923.21) 988.31,-923.21 988.31,-984.25 cw(c945.01,-984.25) 945.01,-1027.56 894.54,-1027.56 ccw(c894.54,-1051.18) 870.91,-1051.18 870.91,-1055.49 ccw(c878.41,-1055.49) v2(878.41,-1062.99)
S33_48.S33_N: P5.11 U16.F20 | length 1527.7
  Top Layer w5: v1(-236.22,354.33) U16.F20@-216.54,334.65 ; v2(-223.92,1736.22) cw(c-231.82,1736.22) -226.23,1730.63 -228.38,1728.48 ccw(c-221.76,1721.87) -231.12,1721.87 ccw(c-223.71,1721.87) -228.95,1716.63 ccw(c-226.41,1719.18) -226.41,1715.58 cw(c-226.41,1711.99) -223.87,1714.53 -222.29,1712.95 cw(c-228.63,1706.62) -219.67,1706.62 P5.11@-219.67,1673.83
  Int2 (Sign) w3: v1(-236.22,354.33) -236.22,346.52 cw(c-244.09,346.52) -244.09,338.65 cw(c-244.09,346.52) -251.97,346.52 -251.97,1577.48 -251.97,1664.09 cw(c-219.21,1664.09) -242.37,1687.26 -242.33,1687.3 ccw(c-268.68,1713.65) -231.42,1713.65 -231.42,1718.11 cw(c-212.47,1718.11) -225.87,1731.51 ccw(c-230.58,1736.22) v2(-223.92,1736.22)
S33_48.S33_P: P5.9 U16.F19 | length 1540.3
  Top Layer w5: P5.9@-251.17,1673.83 -251.17,1706.62 cw(c-242.21,1706.62) -248.54,1712.96 -246.97,1714.53 cw(c-244.43,1711.99) -244.43,1715.58 ccw(c-244.43,1719.18) -241.89,1716.63 ccw(c-247.12,1721.87) -239.72,1721.87 ccw(c-249.08,1721.87) -242.45,1728.48 -244.61,1730.64 cw(c-239.02,1736.22) v2(-246.92,1736.22) ; v1(-236.22,314.96) U16.F19@-216.54,295.28
  Int2 (Sign) w3: v2(-246.92,1736.22) ccw(c-240.26,1736.22) -244.97,1731.51 cw(c-258.37,1718.11) -239.42,1718.11 -239.42,1713.71 cw(c-268.82,1713.71) -248.03,1692.91 ccw(c-219.31,1664.14) -259.97,1664.14 -259.97,1577.46 -259.97,346.52 ccw(c-244.09,346.52) -244.09,330.65 cw(c-244.09,322.77) -236.22,322.77 v1(-236.22,314.96)
S33_48.S34_N: P5.13 U16.D22 | length 1308.8
  Top Layer w5: U16.D22@-295.28,413.39 ccw(c-295.28,429.07) -279.59,429.07 -279.59,1313.01 cw(c-171.69,1313.01) -247.99,1389.31 ; -247.96,1389.34 -205.72,1431.57 ccw(c-276.44,1502.28) -176.44,1502.28 -176.44,1626.83 ccw(c-181.44,1626.83) -177.89,1630.36 -178.19,1630.66 ccw(c-181.02,1627.82) -181.02,1631.83 cw(c-181.02,1635.84) -183.86,1633.01 cw(c-173.42,1643.45) -188.19,1643.45 P5.13@-188.19,1673.83
S33_48.S34_P: P5.15 U16.E22 | length 1308.8
  Top Layer w5: U16.E22@-255.91,413.39 cw(c-255.91,429.07) -271.59,429.07 -271.59,1312.97 cw(c-171.59,1312.97) -242.3,1383.68 -199.93,1426.06 ccw(c-275.95,1502.08) -168.44,1502.08 -168.44,1626.83 cw(c-163.44,1626.83) -166.97,1630.37 -166.68,1630.66 cw(c-163.85,1627.82) -163.85,1631.83 ccw(c-163.85,1635.84) -161.01,1633.01 ccw(c-171.45,1643.45) -156.69,1643.45 P5.15@-156.69,1673.83
S33_48.S35_N: P5.19 U16.G22 | length 1333.9
  Top Layer w5: U16.G22@-177.17,413.39 -177.17,405.57 cw(c-185.04,405.57) -185.04,397.7 cw(c-185.04,405.57) -192.91,405.57 -192.91,1281.41 cw(c-92.91,1281.41) -163.62,1352.12 -137.04,1378.71 ccw(c-213.34,1455.01) -105.44,1455.01 -105.44,1626.42 cw(c-99.44,1626.42) -103.68,1630.66 cw(c-100.85,1627.82) -100.85,1631.83 ccw(c-100.85,1635.84) -98.01,1633.01 -96.44,1634.58 ccw(c-103.07,1641.22) -93.69,1641.22 P5.19@-93.69,1673.83
S33_48.S35_P: P5.17 U16.G21 | length 1346.4
  Top Layer w5: U16.G21@-177.17,374.02 -177.17,381.83 ccw(c-185.04,381.83) -185.04,389.7 cw(c-185.04,405.57) -200.91,405.57 -200.91,1281.45 cw(c-93.01,1281.45) -169.31,1357.75 -142.72,1384.34 ccw(c-213.44,1455.05) -113.44,1455.05 -113.44,1626.42 ccw(c-119.43,1626.42) -115.19,1630.66 ccw(c-118.02,1627.82) -118.02,1631.83 cw(c-118.02,1635.84) -120.86,1633.01 -122.44,1634.58 cw(c-115.8,1641.22) -125.19,1641.22 P5.17@-125.19,1673.83
S33_48.S36_N: P5.21 U16.H22 | length 1296.1
  Top Layer w5: U16.H22@-137.8,413.39 ccw(c-137.8,429.07) -122.11,429.07 -122.11,452.76 -122.11,1258.45 cw(c-14.35,1258.45) -90.55,1334.65 -78.74,1346.46 ccw(c-147.03,1414.75) -50.45,1414.75 -50.45,1626.42 ccw(c-56.44,1626.42) -52.21,1630.66 ccw(c-55.04,1627.82) -55.04,1631.83 cw(c-55.04,1635.84) -57.88,1633.01 -59.45,1634.58 cw(c-52.81,1641.22) -62.2,1641.22 P5.21@-62.2,1673.83
S33_48.S36_P: P5.23 U16.J22 | length 1296.1
  Top Layer w5: U16.J22@-98.43,413.39 cw(c-98.43,429.07) -114.11,429.07 -114.11,452.76 -114.11,1258.35 cw(c-14.11,1258.35) -84.82,1329.06 -72.94,1340.94 ccw(c-146.55,1414.55) -42.45,1414.55 -42.45,1626.42 cw(c-36.46,1626.42) -40.7,1630.66 cw(c-37.86,1627.82) -37.86,1631.83 ccw(c-37.86,1635.84) -35.03,1633.01 -33.45,1634.58 ccw(c-40.09,1641.22) -30.7,1641.22 P5.23@-30.7,1673.83
S33_48.S37_N: P5.27 U16.E18 | length 1841.2
  Top Layer w5: v1(-275.59,275.59) U16.E18@-255.91,255.91 ; v2(28.05,1734.28) cw(c20.98,1734.28) 25.98,1729.28 22.39,1725.7 ccw(c26.85,1721.24) 20.55,1721.24 ccw(c26.54,1721.24) 22.3,1717.01 ccw(c25.14,1719.84) 25.14,1715.83 cw(c25.14,1711.82) 27.97,1714.66 29.55,1713.08 cw(c22.91,1706.44) 32.3,1706.44 P5.27@32.3,1673.83
  Int2 (Sign) w3: v1(-275.59,275.59) -267.78,275.59 ccw(c-267.78,283.46) -259.91,283.46 cw(c-244.03,283.46) -244.03,299.34 -232.28,299.34 ccw(c-232.28,311.15) -220.47,311.15 -220.47,1017.01 -220.6,1017.13 -220.6,1659.99 cw(c-112.75,1659.99) -112.75,1767.84 0.45,1767.84 cw(c0.45,1747.74) 20.55,1747.74 ; 20.55,1747.7 ccw(c28.29,1747.74) v2@22.81,1742.27
S33_48.S37_P: P5.25 U16.F18 | length 1816
  Top Layer w5: v1(-236.22,275.59) U16.F18@-216.54,255.91 ; P5.25@0.8,1673.83 0.8,1706.44 cw(c10.19,1706.44) 3.55,1713.08 5.12,1714.66 cw(c7.96,1711.82) 7.96,1715.83 ccw(c7.96,1719.84) 10.79,1717.01 ccw(c6.56,1721.24) 12.55,1721.24 ccw(c6.25,1721.24) 10.71,1725.69 7.12,1729.28 cw(c12.12,1734.28) v2(5.05,1734.28)
  Int2 (Sign) w3: v1(-236.22,275.59) -244.03,275.59 cw(c-244.03,283.46) -251.91,283.46 cw(c-244.03,283.46) -244.03,291.34 -232.28,291.34 ccw(c-232.28,311.15) -212.47,311.15 -212.47,1020.9 -212.6,1021.03 -212.6,1551.18 -212.6,1659.84 cw(c-112.6,1659.84) -112.6,1759.84 0.41,1759.84 cw(c0.41,1747.7) 12.55,1747.7 cw(c4.91,1747.7) v2@10.31,1742.3
S33_48.S38_N: P5.29 U16.G20 | length 1465
  Top Layer w5: v1(-196.85,354.33) U16.G20@-177.17,334.65 ; P5.29@63.78,1673.83 63.78,1641.04 ccw(c72.74,1641.04) 66.4,1634.71 67.98,1633.13 ccw(c70.52,1635.68) 70.52,1632.08 cw(c70.52,1628.49) 73.06,1631.03 cw(c67.83,1625.79) 75.23,1625.79 cw(c62.96,1625.79) 71.64,1617.12 70.35,1615.82 ccw(c75.93,1610.24) v2(68.03,1610.24)
  Int2 (Sign) w3: v1(-196.85,354.33) ccw(c-196.85,370.02) -181.17,370.02 -181.17,1199.34 cw(c-73.27,1199.34) -181.17,1199.48 cw(c-73.27,1199.34) -149.56,1275.63 57.75,1482.95 ccw(c14.82,1525.88) 75.53,1525.88 75.53,1592.13 ccw(c56.58,1592.13) 69.98,1605.53 cw(c74.69,1610.24) v2(68.03,1610.24)
S33_48.S38_P: P5.31 U16.H20 | length 1465
  Top Layer w5: v1(-157.48,354.33) U16.H20@-137.8,334.65 ; v2(91.03,1610.24) ccw(c83.13,1610.24) 88.73,1615.81 87.42,1617.12 cw(c96.1,1625.79) 83.83,1625.79 cw(c91.24,1625.79) 86,1631.03 cw(c88.54,1628.49) 88.54,1632.08 ccw(c88.54,1635.68) 91.08,1633.13 92.66,1634.71 ccw(c86.32,1641.04) 95.28,1641.04 P5.31@95.28,1673.83
  Int2 (Sign) w3: v1(-157.48,354.33) cw(c-157.48,370.02) -173.17,370.02 -173.17,1199.3 cw(c-73.17,1199.3) -143.88,1270.01 63.52,1477.41 ccw(c15.22,1525.71) 83.53,1525.71 83.53,1592.13 cw(c102.48,1592.13) 89.08,1605.53 ccw(c84.37,1610.24) v2(91.03,1610.24)
S33_48.S39_N: P5.35 U16.J17 | length 1944.5
  Top Layer w5: v1(-118.11,236.22) U16.J17@-98.43,216.54 ; v2(154.03,1734.28) cw(c146.13,1734.28) 151.72,1728.69 148.59,1725.57 ccw(c152.87,1721.31) 146.83,1721.31 ccw(c152.87,1721.31) 148.6,1717.03 149,1716.63 ccw(c151.54,1719.18) 151.54,1715.58 cw(c151.54,1711.99) 154.08,1714.53 155.66,1712.95 cw(c149.32,1706.62) 158.28,1706.62 P5.35@158.28,1673.83
  Int2 (Sign) w3: v1(-118.11,236.22) -110.3,236.22 ccw(c-110.3,244.09) -102.43,244.09 ccw(c-110.3,244.09) -110.3,251.97 -118.24,251.97 cw(c-118.24,275.59) -141.86,275.59 -141.86,1155.47 cw(c-33.96,1155.47) -141.86,1155.62 cw(c-33.96,1155.47) -110.25,1231.77 230.55,1572.58 ccw(c159.84,1643.29) 259.84,1643.29 259.84,1734.49 ccw(c230.55,1734.49) 230.55,1763.78 168.53,1763.78 ccw(c168.53,1741.78) 146.53,1741.78 ccw(c154.03,1741.78) v2(154.03,1734.28)
S33_48.S39_P: P5.33 U16.K17 | length 1969.7
  Top Layer w5: v1(-78.74,236.22) U16.K17@-59.06,216.54 ; P5.33@126.78,1673.83 126.78,1706.62 cw(c135.74,1706.62) 129.41,1712.96 130.98,1714.53 cw(c133.52,1711.99) 133.52,1715.58 ccw(c133.52,1719.18) 136.06,1716.63 136.46,1717.03 ccw(c132.19,1721.31) 138.23,1721.31 ccw(c132.19,1721.31) 136.47,1725.57 133.34,1728.7 cw(c138.93,1734.28) v2(131.03,1734.28)
  Int2 (Sign) w3: v1(-78.74,236.22) -86.55,236.22 cw(c-86.55,244.09) -94.43,244.09 ccw(c-110.3,244.09) -110.3,259.97 -118.24,259.97 cw(c-118.24,275.59) -133.86,275.59 -133.86,1155.43 cw(c-33.86,1155.43) -104.57,1226.14 236.24,1566.95 ccw(c159.94,1643.25) 236.3,1567.01 ccw(c159.94,1643.25) 267.84,1643.25 267.84,1734.49 ccw(c230.55,1734.49) 230.55,1771.78 168.53,1771.78 ccw(c168.53,1741.78) 138.53,1741.78 cw(c131.03,1741.78) v2(131.03,1734.28)
S33_48.S40_N: P5.37 U16.C17 | length 1896.5
  Top Layer w5: v1(-354.33,236.22) U16.C17@-334.65,216.54 ; P5.37@189.76,1673.83 189.76,1706.62 cw(c198.73,1706.62) 192.39,1712.96 193.97,1714.53 cw(c196.5,1711.99) 196.5,1715.58 ccw(c196.5,1719.18) 199.05,1716.63 199.45,1717.03 ccw(c195.17,1721.31) 201.21,1721.31 ccw(c195.17,1721.31) 199.45,1725.57 196.32,1728.7 cw(c201.91,1734.28) v2(194.01,1734.28)
  Int6 (Sign) w3: v1(-354.33,236.22) ccw(c-354.33,251.91) -338.65,251.91 -338.65,275.59 cw(c-314.96,275.59) -314.96,299.28 -196.79,299.28 ccw(c-196.79,314.96) -181.1,314.96 -181.1,1250.08 cw(c-73.2,1250.08) -149.53,1326.35 ; -149.5,1326.38 179.38,1655.26 ccw(c125.95,1708.7) 201.52,1708.7 201.51,1716.17 ccw(c182.57,1716.17) 195.96,1729.57 cw(c200.67,1734.28) v2(194.01,1734.28)
S33_48.S40_P: P5.39 U16.D17 | length 1896.5
  Top Layer w5: v1(-314.96,236.22) U16.D17@-295.28,216.54 ; v2(217.01,1734.28) cw(c209.12,1734.28) 214.7,1728.69 211.58,1725.57 ccw(c215.86,1721.31) 209.81,1721.31 ccw(c215.86,1721.31) 211.58,1717.03 211.98,1716.63 ccw(c214.53,1719.18) 214.53,1715.58 cw(c214.53,1711.99) 217.06,1714.53 218.65,1712.95 cw(c212.3,1706.62) 221.26,1706.62 P5.39@221.26,1673.83
  Int6 (Sign) w3: v1(-314.96,236.22) cw(c-314.96,251.91) -330.65,251.91 -330.65,275.59 cw(c-314.96,275.59) -314.96,291.28 -196.79,291.28 ccw(c-196.79,314.96) -173.1,314.96 -173.1,1250.04 cw(c-73.1,1250.04) -143.81,1320.75 185.13,1649.7 ccw(c126.26,1708.57) 209.51,1708.57 209.51,1716.17 cw(c228.46,1716.17) 215.07,1729.57 ccw(c210.36,1734.28) v2(217.01,1734.28)
S33_48.S41_N: P5.43 U16.K19 | length 1770
  Top Layer w5: v1(-78.74,314.96) U16.K19@-59.06,295.28 ; v2(437.48,1736.22) cw(c429.58,1736.22) 435.17,1730.63 433.02,1728.48 ccw(c439.64,1721.87) 430.28,1721.87 ccw(c437.69,1721.87) 432.45,1716.63 ccw(c434.99,1719.18) 434.99,1715.58 cw(c434.99,1711.99) 437.53,1714.53 439.11,1712.95 cw(c432.77,1706.62) 441.73,1706.62 P5.43@441.73,1673.83
  Int2 (Sign) w3: v1(-78.74,314.96) -78.74,307.15 cw(c-86.61,307.15) -86.61,299.28 cw(c-86.61,307.15) -94.49,307.15 -94.49,1108.68 cw(c5.51,1108.68) -65.2,1179.39 399.22,1643.81 ccw(c324.96,1718.07) 429.98,1718.07 ; 429.98,1718.11 cw(c448.93,1718.11) 435.53,1731.51 ccw(c430.82,1736.22) v2(437.48,1736.22)
S33_48.S41_P: P5.41 U16.K18 | length 1782.5
  Top Layer w5: v1(-78.74,275.59) U16.K18@-59.06,255.91 ; P5.41@410.23,1673.83 410.23,1706.62 cw(c419.19,1706.62) 412.86,1712.96 414.43,1714.53 cw(c416.97,1711.99) 416.97,1715.58 ccw(c416.97,1719.18) 419.51,1716.63 ccw(c414.28,1721.87) 421.68,1721.87 ccw(c412.32,1721.87) 418.95,1728.48 416.79,1730.64 cw(c422.38,1736.22) v2(414.48,1736.22)
  Int2 (Sign) w3: v1(-78.74,275.59) -78.74,283.4 ccw(c-86.61,283.4) -86.61,291.28 cw(c-86.61,307.15) -102.49,307.15 -102.49,1108.72 cw(c5.41,1108.72) -70.88,1185.02 ; -70.86,1185.05 393.54,1649.44 ccw(c324.87,1718.11) 421.98,1718.11 ccw(c403.03,1718.11) 416.43,1731.51 cw(c421.14,1736.22) v2(414.48,1736.22)
S33_48.S42_N: P5.45 U16.K16 | length 1866.4
  Top Layer w5: v1(-78.74,196.85) U16.K16@-59.06,177.17 ; P5.45@473.21,1673.83 473.21,1706.62 cw(c482.18,1706.62) 475.84,1712.96 477.42,1714.53 cw(c479.95,1711.99) 479.95,1715.58 ccw(c479.95,1719.18) 482.5,1716.63 ccw(c477.26,1721.87) 484.66,1721.87 ccw(c475.3,1721.87) 481.93,1728.48 479.77,1730.64 cw(c485.36,1736.22) v2(477.46,1736.22)
  Int2 (Sign) w3: v1(-78.74,196.85) ccw(c-78.74,212.54) -63.06,212.54 -63.06,1065.48 cw(c44.84,1065.48) -31.45,1141.78 455.68,1628.9 ccw(c384.97,1699.61) 484.97,1699.61 484.96,1718.11 ccw(c466.02,1718.11) 479.41,1731.51 cw(c484.12,1736.22) v2(477.46,1736.22)
S33_48.S42_P: P5.47 U16.L16 | length 1866.4
  Top Layer w5: v1(-39.37,196.85) U16.L16@-19.69,177.17 ; v2(500.46,1736.22) cw(c492.57,1736.22) 498.15,1730.63 496,1728.48 ccw(c502.63,1721.87) 493.26,1721.87 ccw(c500.67,1721.87) 495.43,1716.63 ccw(c497.98,1719.18) 497.98,1715.58 cw(c497.98,1711.99) 500.51,1714.53 502.1,1712.95 cw(c495.75,1706.62) 504.71,1706.62 P5.47@504.71,1673.83
  Int2 (Sign) w3: v1(-39.37,196.85) cw(c-39.37,212.54) -55.06,212.54 -55.06,1065.44 cw(c44.94,1065.44) -25.77,1136.15 461.44,1623.35 ccw(c385.32,1699.47) 492.96,1699.47 492.96,1718.11 cw(c511.91,1718.11) 498.52,1731.51 ccw(c493.81,1736.22) v2(500.46,1736.22)
S33_48.S43_N: P5.51 U16.K22 | length 1558.4
  Top Layer w5: U16.K22@-59.06,413.39 -59.06,401.64 cw(c-62.99,401.64) -62.99,397.7 cw(c-62.99,409.51) -74.8,409.51 -74.8,421.94 cw(c-47.92,421.94) -66.93,440.94 -66.81,441.06 ccw(c-95.35,469.6) -54.99,469.6 -54.99,947.39 cw(c45.01,947.39) -25.7,1018.1 540.22,1584.02 ccw(c502.2,1622.04) 555.96,1622.04 555.96,1626.42 cw(c561.96,1626.42) 557.72,1630.66 cw(c560.55,1627.82) 560.55,1631.83 ccw(c560.55,1635.84) 563.39,1633.01 564.96,1634.58 ccw(c558.33,1641.22) 567.71,1641.22 P5.51@567.71,1673.83
S33_48.S43_P: P5.49 U16.K21 | length 1570.9
  Top Layer w5: U16.K21@-59.06,374.02 -59.06,385.76 ccw(c-62.99,385.76) -62.99,389.7 cw(c-62.99,409.51) -82.8,409.51 -82.8,422.05 cw(c-48.19,422.05) -72.67,446.52 -72.59,446.6 ccw(c-95.75,469.76) -62.99,469.76 -62.99,947.43 cw(c44.91,947.43) -62.99,947.58 cw(c44.91,947.43) -31.39,1023.73 534.55,1589.67 ccw(c502.18,1622.05) 547.96,1622.05 547.96,1626.42 ccw(c541.97,1626.42) 546.21,1630.66 ccw(c543.38,1627.82) 543.38,1631.83 cw(c543.38,1635.84) 540.54,1633.01 538.96,1634.58 cw(c545.6,1641.22) 536.21,1641.22 P5.49@536.21,1673.83
S33_48.S44_N: P5.53 U16.L21 | length 1573.8
  Top Layer w5: U16.L21@-19.69,374.02 ccw(c-19.69,389.7) -4,389.7 -4,426.02 ccw(c-30.67,426.02) -11.81,444.88 -11.86,444.93 cw(c16.83,473.63) -23.75,473.63 -23.75,896.12 cw(c84.15,896.12) 7.86,972.42 581.66,1546.23 ccw(c510.95,1616.94) 610.95,1616.94 610.95,1626.42 ccw(c604.96,1626.42) 609.19,1630.66 ccw(c606.36,1627.82) 606.36,1631.83 cw(c606.36,1635.84) 603.52,1633.01 601.95,1634.58 cw(c608.59,1641.22) 599.2,1641.22 P5.53@599.2,1673.83
S33_48.S44_P: P5.55 U16.M21 | length 1573.8
  Top Layer w5: -6.13,450.52 cw(c-30.59,426.06) 4,426.06 4,389.7 ccw(c19.69,389.7) U16.M21@19.69,374.02 ; -6.15,450.54 cw(c17.01,473.7) -15.75,473.7 -15.75,896.08 cw(c84.25,896.08) 13.54,966.79 587.34,1540.6 ccw(c511.05,1616.9) 618.95,1616.9 618.95,1626.42 cw(c624.94,1626.42) 620.7,1630.66 cw(c623.54,1627.82) 623.54,1631.83 ccw(c623.54,1635.84) 626.37,1633.01 627.95,1634.58 ccw(c621.31,1641.22) 630.7,1641.22 P5.55@630.7,1673.83
S33_48.S45_N: P5.59 U16.R19 | length 1745
  Top Layer w5: U16.R19@137.8,295.28 v1(157.48,314.96) ; v2(689.45,1736.22) cw(c681.55,1736.22) 687.13,1730.63 684.98,1728.48 ccw(c691.61,1721.87) 682.25,1721.87 ccw(c689.65,1721.87) 684.42,1716.63 ccw(c686.96,1719.18) 686.96,1715.58 cw(c686.96,1711.99) 689.49,1714.53 691.08,1712.95 cw(c684.74,1706.62) 693.7,1706.62 P5.59@693.7,1673.83
  Int2 (Sign) w3: v1(157.48,314.96) cw(c157.48,330.65) 141.8,330.65 141.8,515.75 ccw(c133.8,515.75) 141.75,516.61 cw(c144.73,516.93) 141.73,516.91 141.73,520.46 141.73,963.01 cw(c241.73,963.01) 171.02,1033.72 650.34,1513.05 ccw(c574.05,1589.34) 681.95,1589.34 681.95,1718.11 cw(c700.9,1718.11) 687.5,1731.51 ccw(c682.79,1736.22) v2(689.45,1736.22)
S33_48.S45_P: P5.57 U16.P19 | length 1745
  Top Layer w5: U16.P19@98.43,295.28 v1(118.11,314.96) ; P5.57@662.2,1673.83 662.2,1706.62 cw(c671.16,1706.62) 664.82,1712.96 666.4,1714.53 cw(c668.94,1711.99) 668.94,1715.58 ccw(c668.94,1719.18) 671.48,1716.63 ccw(c666.24,1721.87) 673.65,1721.87 ccw(c664.28,1721.87) 670.91,1728.48 668.75,1730.64 cw(c674.35,1736.22) v2(666.45,1736.22)
  Int2 (Sign) w3: v1(118.11,314.96) ccw(c118.11,330.65) 133.8,330.65 133.8,515.75 133.73,515.81 133.73,963.05 cw(c241.63,963.05) 165.34,1039.35 644.66,1518.67 ccw(c573.95,1589.39) 673.95,1589.39 673.95,1718.11 ccw(c655,1718.11) 668.4,1731.51 cw(c673.11,1736.22) v2(666.45,1736.22)
S33_48.S46_N: P5.61 U16.M22 | length 1557.6
  Top Layer w5: U16.M22@19.69,413.39 ccw(c19.69,429.07) 35.37,429.07 35.37,452.76 35.37,837.13 cw(c143.27,837.13) 66.94,913.4 ; 66.97,913.43 712.38,1558.84 ccw(c653.1,1618.11) 736.93,1618.11 736.93,1626.42 ccw(c730.94,1626.42) 735.18,1630.66 ccw(c732.34,1627.82) 732.34,1631.83 cw(c732.34,1635.84) 729.51,1633.01 727.93,1634.58 cw(c734.57,1641.22) 725.18,1641.22 P5.61@725.18,1673.83
S33_48.S46_P: P5.63 U16.N22 | length 1557.6
  Top Layer w5: U16.N22@59.06,413.39 cw(c59.06,429.07) 43.37,429.07 43.37,452.76 43.37,837.09 cw(c143.37,837.09) 72.6,907.74 cw(c143.37,837.09) 72.66,907.8 718.07,1553.22 ccw(c653.24,1618.06) 744.93,1618.06 744.93,1626.42 cw(c750.92,1626.42) 746.69,1630.66 cw(c749.52,1627.82) 749.52,1631.83 ccw(c749.52,1635.84) 752.36,1633.01 753.93,1634.58 ccw(c747.29,1641.22) 756.68,1641.22 P5.63@756.68,1673.83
